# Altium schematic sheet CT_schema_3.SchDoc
size 218 x 258 mm
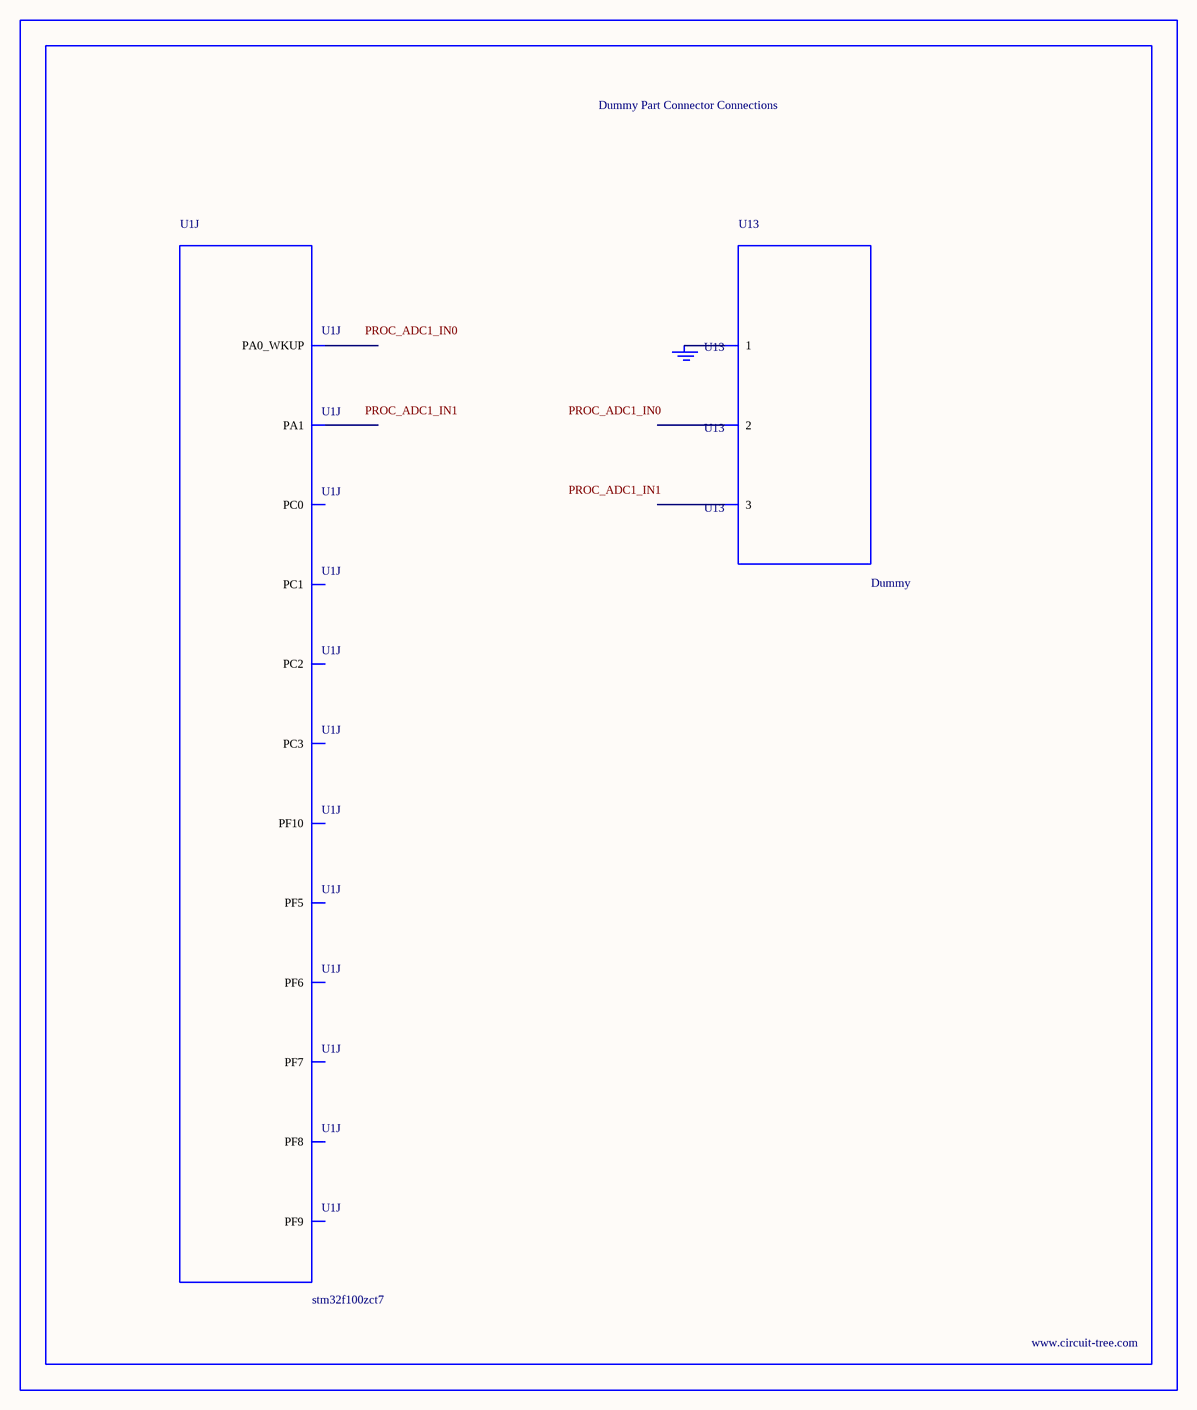
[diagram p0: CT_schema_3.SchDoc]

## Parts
BORDER2  (no value)
GND_INSTANCE_2_0  (no value)
U1  stm32f100zct7  [LQFP144]  (part J of 10)
U13  Dummy  [DUMMY_PACKAGE_128]

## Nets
NetGND_INSTANCE_2_0_0: GND_INSTANCE_2_0.0(GND) U13.1

Not connected (* = marked no-connect by the designer): U1 15(PF5) 18(PF6) 19(PF7) 20(PF8) 21(PF9) 22(PF10) 26(PC0) 27(PC1) 28(PC2) 29(PC3) 34(PA0_WKUP) 35(PA1); U13 2 3

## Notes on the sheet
- Labels drawn without touching a wire or pin: PROC_ADC1_IN0, PROC_ADC1_IN1

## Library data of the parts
BORDER2 = BORDER_PAGE2
GND_INSTANCE_2_0 = GND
